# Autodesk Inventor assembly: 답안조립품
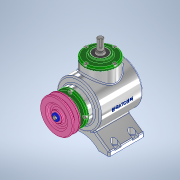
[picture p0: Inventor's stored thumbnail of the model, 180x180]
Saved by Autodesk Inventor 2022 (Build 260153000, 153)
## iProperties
Created: 2023-04
Part Number: 답안조립품
Document SubType Name: Assembly
Designer: ADMIN_PC
Author: ADMIN_PC
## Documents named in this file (17)
- C:\Users\ADMIN_PC\Desktop\730411V1002\답안조립품.iam
- C:\Users\ADMIN_PC\Desktop\730411V1002\본체.ipt
- C:\Users\ADMIN_PC\Desktop\730411V1002\커버.ipt
- C:\Users\ADMIN_PC\Desktop\730411V1002\베어링 6203.ipt
- C:\Users\ADMIN_PC\Desktop\730411V1002\오일실 17 x 32 x 8.ipt
- C:\Users\ADMIN_PC\Desktop\730411V1002\메인 축.ipt
- 메인 축.ipt
- C:\Users\ADMIN_PC\Desktop\730411V1002\키 5 x 5 x 14.ipt
- C:\Users\ADMIN_PC\Desktop\730411V1002\메인 베벨기어.ipt
- C:\Users\ADMIN_PC\Desktop\730411V1002\서브 축.ipt
- 서브 축.ipt
- C:\Users\ADMIN_PC\Desktop\730411V1002\키 4 x 4 x 14.ipt
- C:\Users\ADMIN_PC\Desktop\730411V1002\서브 베벨기어.ipt
- C:\Users\ADMIN_PC\Desktop\730411V1002\V-벨트풀리.ipt
- C:\Users\ADMIN_PC\Desktop\730411V1002\볼트 M4 x 10.ipt
- C:\Users\ADMIN_PC\Desktop\730411V1002\와셔 4 x 16.ipt
- C:\Users\ADMIN_PC\Desktop\730411V1002\육각볼트 M4 x 8.ipt
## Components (1 placed, 1 different names)
1. V-벨트풀리:1
